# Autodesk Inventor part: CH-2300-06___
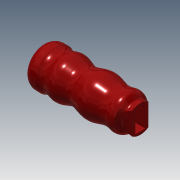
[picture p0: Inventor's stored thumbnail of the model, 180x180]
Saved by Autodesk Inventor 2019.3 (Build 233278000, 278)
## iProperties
Created: 2012-09
Part Number: CH-2300-06___
Material: Ogólny
Document SubType Name: Modeling
Designer: CADENGINEERING4
Density: 1 g/cm^3
Appearance: Czerwona
Author: CADENGINEERING4
Revision Number: ÈÎºÎ
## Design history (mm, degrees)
feature "NONE"
node "Bryła1"
